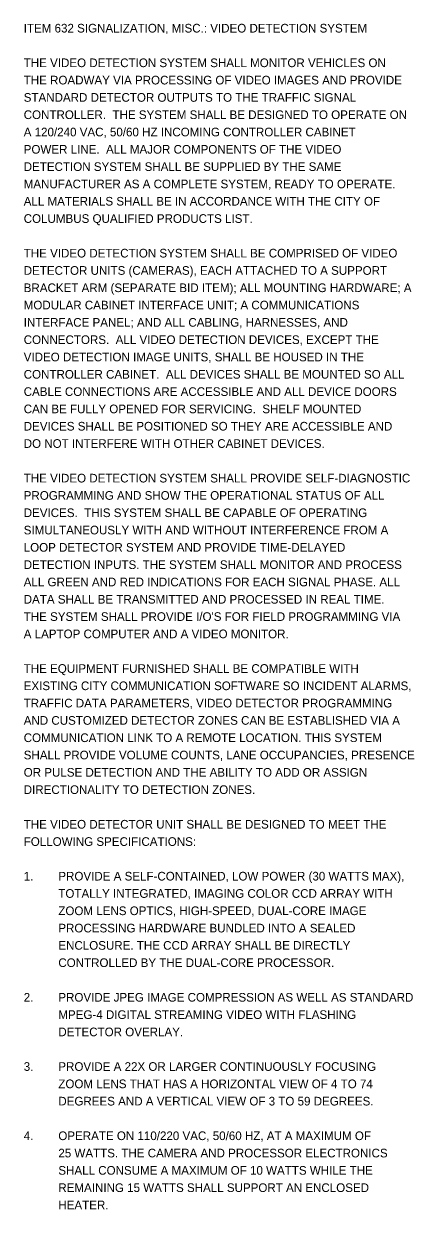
# Model space of a CAD drawing. Extents: x -15.1 to 53.7, y -46.4 to 36.
# Drawn here: x -8.57 to -2.26, y -46.44 to -27.26 of the extents above; entities that cross this region are included whole.
import ezdxf

# ---------------------------------------------------------------- set-up
doc = ezdxf.new("R2010")
doc.units = 0
doc.layers.add('SH_Data', color=7, linetype='Continuous')
doc.layers.add('SH_Text', color=7, linetype='Continuous')

msp = doc.modelspace()

# ---------------------------------------------------------------- texts
at = {"layer": 'SH_Data'}
msp.add_text('ITEM 632 SIGNALIZATION, MISC.: VIDEO DETECTION SYSTEM', height=0.14, rotation=360, dxfattribs=at).set_placement((-8.575, -27.404))
at = {"layer": 'SH_Text'}
for s, p in [('THE VIDEO DETECTION SYSTEM SHALL MONITOR VEHICLES ON ', (-8.575, -27.964)), ('THE ROADWAY VIA PROCESSING OF VIDEO IMAGES AND PROVIDE ', (-8.575, -28.244)), ('STANDARD DETECTOR OUTPUTS TO THE TRAFFIC SIGNAL ', (-8.575, -28.524)), ('CONTROLLER.  THE SYSTEM SHALL BE DESIGNED TO OPERATE ON ', (-8.575, -28.804)), ('A 120/240 VAC, 50/60 HZ INCOMING CONTROLLER CABINET ', (-8.575, -29.084)), ('POWER LINE.  ALL MAJOR COMPONENTS OF THE VIDEO ', (-8.575, -29.364)), ('DETECTION SYSTEM SHALL BE SUPPLIED BY THE SAME ', (-8.575, -29.644)), ('MANUFACTURER AS A COMPLETE SYSTEM, READY TO OPERATE. ', (-8.575, -29.924)), ('ALL MATERIALS SHALL BE IN ACCORDANCE WITH THE CITY OF ', (-8.575, -30.204)), ('COLUMBUS QUALIFIED PRODUCTS LIST.', (-8.575, -30.484)), ('THE VIDEO DETECTION SYSTEM SHALL BE COMPRISED OF VIDEO ', (-8.575, -31.044)), ('DETECTOR UNITS (CAMERAS), EACH ATTACHED TO A SUPPORT ', (-8.575, -31.324)), ('BRACKET ARM (SEPARATE BID ITEM); ALL MOUNTING HARDWARE; A ', (-8.575, -31.604)), ('MODULAR CABINET INTERFACE UNIT; A COMMUNICATIONS ', (-8.575, -31.884)), ('INTERFACE PANEL; AND ALL CABLING, HARNESSES, AND ', (-8.575, -32.164)), ('CONNECTORS.  ALL VIDEO DETECTION DEVICES, EXCEPT THE ', (-8.575, -32.444)), ('VIDEO DETECTION IMAGE UNITS, SHALL BE HOUSED IN THE ', (-8.575, -32.724)), ('CONTROLLER CABINET.  ALL DEVICES SHALL BE MOUNTED SO ALL ', (-8.575, -33.004)), ('CABLE CONNECTIONS ARE ACCESSIBLE AND ALL DEVICE DOORS ', (-8.575, -33.284)), ('CAN BE FULLY OPENED FOR SERVICING.  SHELF MOUNTED ', (-8.575, -33.564)), ('DEVICES SHALL BE POSITIONED SO THEY ARE ACCESSIBLE AND ', (-8.575, -33.844)), ('DO NOT INTERFERE WITH OTHER CABINET DEVICES.', (-8.575, -34.124)), ('THE VIDEO DETECTION SYSTEM SHALL PROVIDE SELF-DIAGNOSTIC ', (-8.575, -34.684)), ('PROGRAMMING AND SHOW THE OPERATIONAL STATUS OF ALL ', (-8.575, -34.964)), ('DEVICES.  THIS SYSTEM SHALL BE CAPABLE OF OPERATING ', (-8.575, -35.244)), ('SIMULTANEOUSLY WITH AND WITHOUT INTERFERENCE FROM A ', (-8.575, -35.524)), ('LOOP DETECTOR SYSTEM AND PROVIDE TIME-DELAYED ', (-8.575, -35.804)), ('DETECTION INPUTS. THE SYSTEM SHALL MONITOR AND PROCESS ', (-8.575, -36.084)), ('ALL GREEN AND RED INDICATIONS FOR EACH SIGNAL PHASE. ALL ', (-8.575, -36.364)), ('DATA SHALL BE TRANSMITTED AND PROCESSED IN REAL TIME. ', (-8.575, -36.644)), ("THE SYSTEM SHALL PROVIDE I/O'S FOR FIELD PROGRAMMING VIA ", (-8.575, -36.924)), ('A LAPTOP COMPUTER AND A VIDEO MONITOR.', (-8.575, -37.204)), ('THE EQUIPMENT FURNISHED SHALL BE COMPATIBLE WITH ', (-8.575, -37.764)), ('EXISTING CITY COMMUNICATION SOFTWARE SO INCIDENT ALARMS, ', (-8.575, -38.044)), ('TRAFFIC DATA PARAMETERS, VIDEO DETECTOR PROGRAMMING ', (-8.575, -38.324)), ('AND CUSTOMIZED DETECTOR ZONES CAN BE ESTABLISHED VIA A ', (-8.575, -38.604)), ('COMMUNICATION LINK TO A REMOTE LOCATION. THIS SYSTEM ', (-8.575, -38.884)), ('SHALL PROVIDE VOLUME COUNTS, LANE OCCUPANCIES, PRESENCE ', (-8.575, -39.164)), ('OR PULSE DETECTION AND THE ABILITY TO ADD OR ASSIGN ', (-8.575, -39.444)), ('DIRECTIONALITY TO DETECTION ZONES. ', (-8.575, -39.724)), ('THE VIDEO DETECTOR UNIT SHALL BE DESIGNED TO MEET THE ', (-8.575, -40.284)), ('FOLLOWING SPECIFICATIONS:', (-8.575, -40.564)), ('1.', (-8.575, -41.124)), ('PROVIDE A SELF-CONTAINED, LOW POWER (30 WATTS MAX), ', (-8.015, -41.124)), ('TOTALLY INTEGRATED, IMAGING COLOR CCD ARRAY WITH ', (-8.015, -41.404)), ('ZOOM LENS OPTICS, HIGH-SPEED, DUAL-CORE IMAGE ', (-8.015, -41.684)), ('PROCESSING HARDWARE BUNDLED INTO A SEALED ', (-8.015, -41.964)), ('ENCLOSURE. THE CCD ARRAY SHALL BE DIRECTLY ', (-8.015, -42.244)), ('CONTROLLED BY THE DUAL-CORE PROCESSOR.', (-8.015, -42.524)), ('2.', (-8.575, -43.084)), ('PROVIDE JPEG IMAGE COMPRESSION AS WELL AS STANDARD ', (-8.015, -43.084)), ('MPEG-4 DIGITAL STREAMING VIDEO WITH FLASHING ', (-8.015, -43.364)), ('DETECTOR OVERLAY.', (-8.015, -43.644)), ('3.', (-8.575, -44.204)), ('PROVIDE A 22X OR LARGER CONTINUOUSLY FOCUSING ', (-8.015, -44.204)), ('ZOOM LENS THAT HAS A HORIZONTAL VIEW OF 4 TO 74 ', (-8.015, -44.484)), ('DEGREES AND A VERTICAL VIEW OF 3 TO 59 DEGREES.', (-8.015, -44.764)), ('4.', (-8.575, -45.324)), ('OPERATE ON 110/220 VAC, 50/60 HZ, AT A MAXIMUM OF ', (-8.015, -45.324)), ('25 WATTS. THE CAMERA AND PROCESSOR ELECTRONICS ', (-8.015, -45.604)), ('SHALL CONSUME A MAXIMUM OF 10 WATTS WHILE THE ', (-8.015, -45.884)), ('REMAINING 15 WATTS SHALL SUPPORT AN ENCLOSED ', (-8.015, -46.164)), ('HEATER.', (-8.015, -46.444))]:
    msp.add_text(s, height=0.14, rotation=360, dxfattribs=at).set_placement(p)

doc.saveas('drawing.dxf')
